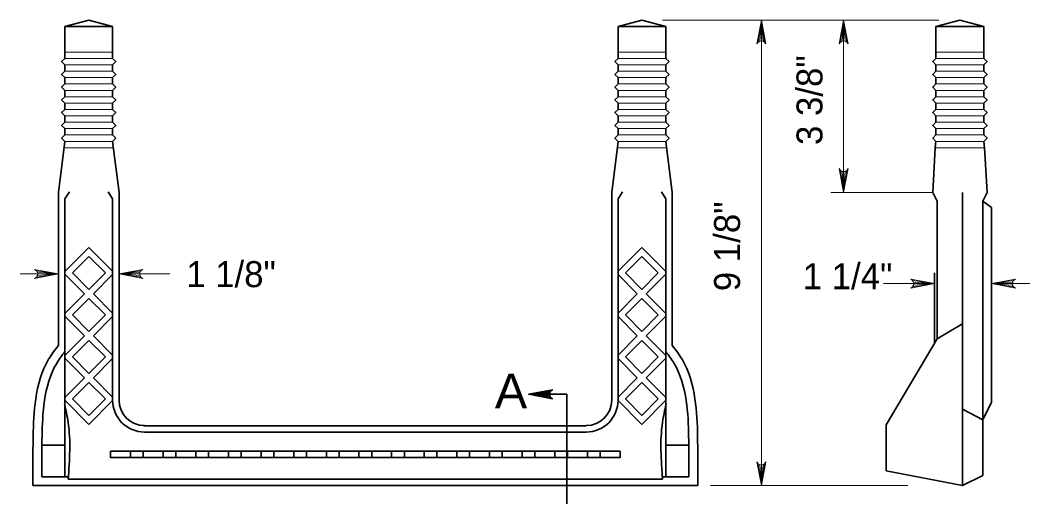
# Model space of a CAD drawing. Extents: x 15 to 140, y -57 to 117.
# Drawn here: x 96.58 to 136.22, y 36.32 to 55.01 of the extents above; entities that cross this region are included whole.
import ezdxf
from ezdxf.enums import TextEntityAlignment as Align

# ---------------------------------------------------------------- set-up
doc = ezdxf.new("R2010")
doc.units = 0
doc.header["$LTSCALE"] = 0.41
for name, color, linetype, lineweight in [('1', 7, 'Continuous', 35), ('10', 7, 'Continuous', 13), ('12', 7, 'Continuous', 53), ('13', 7, 'Continuous', 53), ('6', 7, 'Continuous', 13)]:
    doc.layers.add(name, color=color, linetype=linetype, lineweight=lineweight)

msp = doc.modelspace()

# ---------------------------------------------------------------- linework, layer by layer
at = {"layer": '1'}
for p, q in [((98.332, 54.7556), (100.2119, 54.7556)), ((98.332, 53.5056), (98.332, 54.7556)), ((100.2119, 53.5056), (100.2119, 54.7556)), ((121.9346, 54.7556), (120.0548, 54.7556)), ((120.0548, 53.5056), (120.0548, 54.7556)), ((121.9346, 53.5056), (121.9346, 54.7556)), ((134.4166, 54.7556), (132.5368, 54.7556)), ((132.5368, 53.5056), (132.5368, 54.7556)), ((134.4166, 53.5056), (134.4166, 54.7556)), ((98.332, 53.0056), (98.332, 53.2556)), ((100.2119, 53.0056), (100.2119, 53.2556)), ((120.0548, 53.0056), (120.0548, 53.2556)), ((121.9346, 53.0056), (121.9346, 53.2556)), ((132.5368, 53.0056), (132.5368, 53.2556)), ((134.4166, 53.0056), (134.4166, 53.2556)), ((98.332, 52.5056), (98.332, 52.7556)), ((100.2119, 52.5056), (100.2119, 52.7556)), ((120.0548, 52.5056), (120.0548, 52.7556)), ((121.9346, 52.5056), (121.9346, 52.7556)), ((132.5368, 52.5056), (132.5368, 52.7556)), ((134.4166, 52.5056), (134.4166, 52.7556)), ((98.332, 52.0056), (98.332, 52.2556)), ((100.2119, 52.0056), (100.2119, 52.2556)), ((120.0548, 52.0056), (120.0548, 52.2556)), ((121.9346, 52.0056), (121.9346, 52.2556)), ((132.5368, 52.0056), (132.5368, 52.2556)), ((134.4166, 52.0056), (134.4166, 52.2556)), ((98.332, 51.5056), (98.332, 51.7556)), ((100.2119, 51.5056), (100.2119, 51.7556)), ((120.0548, 51.5056), (120.0548, 51.7556)), ((121.9346, 51.5056), (121.9346, 51.7556)), ((132.5368, 51.5056), (132.5368, 51.7556)), ((134.4166, 51.5056), (134.4166, 51.7556)), ((98.332, 51.0056), (98.332, 51.2556)), ((100.2119, 51.0056), (100.2119, 51.2556)), ((120.0548, 51.0056), (120.0548, 51.2556)), ((121.9346, 51.0056), (121.9346, 51.2556)), ((132.5368, 51.0056), (132.5368, 51.2556)), ((134.4166, 51.0056), (134.4166, 51.2556)), ((98.332, 50.5056), (98.332, 50.7556)), ((100.2119, 50.5056), (100.2119, 50.7556)), ((120.0548, 50.5056), (120.0548, 50.7556)), ((121.9346, 50.5056), (121.9346, 50.7556)), ((132.5368, 50.5056), (132.5368, 50.7556)), ((134.4166, 50.5056), (134.4166, 50.7556)), ((98.082, 48.2556), (98.332, 50.2556)), ((100.4619, 48.2556), (100.2119, 50.2556)), ((119.8048, 48.2556), (120.0548, 50.2556)), ((122.1846, 48.2556), (121.9346, 50.2556)), ((132.4118, 48.2556), (132.5055, 50.0056)), ((132.5055, 50.0056), (132.5368, 50.2556)), ((134.4166, 50.2556), (134.4478, 50.0056)), ((134.5416, 48.2556), (134.4478, 50.0056)), ((98.082, 42.2556), (98.082, 48.2556)), ((98.332, 48.0056), (98.5123, 48.2805)), ((98.332, 37.1056), (98.332, 48.0056)), ((100.2119, 48.0056), (100.0316, 48.2805)), ((100.2119, 40.107), (100.2119, 48.0056)), ((100.4619, 40.1074), (100.4619, 48.2556)), ((119.8048, 40.1074), (119.8048, 48.2556)), ((120.0548, 48.0056), (120.2351, 48.2805)), ((120.0548, 40.107), (120.0548, 48.0056)), ((121.9346, 48.0056), (121.7544, 48.2805)), ((121.9346, 37.1056), (121.9346, 48.0056)), ((122.1846, 42.2556), (122.1846, 48.2556)), ((133.582, 36.7556), (133.582, 48.2556)), ((134.3713, 47.9131), (134.7213, 47.6553)), ((134.7213, 47.6553), (134.7213, 40.0341)), ((132.482, 42.3374), (132.482, 45.1017)), ((132.582, 42.5056), (133.5496, 43.0918)), ((130.582, 39.1423), (132.582, 42.5056)), ((134.3713, 39.3341), (133.6079, 39.7354)), ((134.3713, 39.3341), (134.7213, 40.0341)), ((101.4213, 39.1056), (118.8048, 39.1056)), ((101.4619, 38.8556), (118.8048, 38.8556)), ((130.582, 37.3387), (130.582, 39.1423)), ((97.4369, 38.3417), (98.332, 38.3417)), ((100.1333, 37.8549), (100.1333, 38.1049)), ((100.1333, 38.1049), (120.1333, 38.1049)), ((108.6024, 37.8549), (108.6024, 38.1049)), ((111.6642, 37.8549), (111.6642, 38.1049)), ((120.1333, 37.8549), (120.1333, 38.1049)), ((122.8298, 38.3417), (121.9346, 38.3417)), ((97.082, 36.7556), (97.082, 37.7556)), ((97.432, 37.1056), (97.432, 37.7556)), ((100.1333, 37.8549), (120.1333, 37.8549)), ((122.8346, 37.1056), (122.8346, 37.7556)), ((123.1846, 36.7556), (123.1846, 37.7556)), ((133.582, 36.7556), (130.582, 37.3387)), ((97.432, 37.1056), (98.4657, 37.1056)), ((98.4653, 37.0056), (121.8014, 37.0056)), ((122.8346, 37.1056), (121.801, 37.1056)), ((133.582, 36.7556), (134.3713, 37.1502)), ((97.082, 36.7556), (123.1846, 36.7556))]:
    msp.add_line(p, q, dxfattribs=at)
for points in [[(98.332, 54.7556), (99.2719, 55.0056), (100.2119, 54.7556)], [(121.9346, 54.7556), (120.9947, 55.0056), (120.0548, 54.7556)], [(134.4166, 54.7556), (133.4767, 55.0056), (132.5368, 54.7556)], [(98.332, 53.5056), (98.207, 53.3806), (98.332, 53.2556)], [(100.2119, 53.5056), (100.3369, 53.3806), (100.2119, 53.2556)], [(120.0548, 53.5056), (119.9298, 53.3806), (120.0548, 53.2556)], [(121.9346, 53.5056), (122.0596, 53.3806), (121.9346, 53.2556)], [(132.5368, 53.5056), (132.4118, 53.3806), (132.5368, 53.2556)], [(134.4166, 53.5056), (134.5416, 53.3806), (134.4166, 53.2556)], [(98.332, 53.0056), (98.207, 52.8806), (98.332, 52.7556)], [(100.2119, 53.0056), (100.3369, 52.8806), (100.2119, 52.7556)], [(120.0548, 53.0056), (119.9298, 52.8806), (120.0548, 52.7556)], [(121.9346, 53.0056), (122.0596, 52.8806), (121.9346, 52.7556)], [(132.5368, 53.0056), (132.4118, 52.8806), (132.5368, 52.7556)], [(134.4166, 53.0056), (134.5416, 52.8806), (134.4166, 52.7556)], [(98.332, 52.5056), (98.207, 52.3806), (98.332, 52.2556)], [(100.2119, 52.5056), (100.3369, 52.3806), (100.2119, 52.2556)], [(120.0548, 52.5056), (119.9298, 52.3806), (120.0548, 52.2556)], [(121.9346, 52.5056), (122.0596, 52.3806), (121.9346, 52.2556)], [(132.5368, 52.5056), (132.4118, 52.3806), (132.5368, 52.2556)], [(134.4166, 52.5056), (134.5416, 52.3806), (134.4166, 52.2556)], [(98.332, 52.0056), (98.207, 51.8806), (98.332, 51.7556)], [(100.2119, 52.0056), (100.3369, 51.8806), (100.2119, 51.7556)], [(120.0548, 52.0056), (119.9298, 51.8806), (120.0548, 51.7556)], [(121.9346, 52.0056), (122.0596, 51.8806), (121.9346, 51.7556)], [(132.5368, 52.0056), (132.4118, 51.8806), (132.5368, 51.7556)], [(134.4166, 52.0056), (134.5416, 51.8806), (134.4166, 51.7556)], [(98.332, 51.5056), (98.207, 51.3806), (98.332, 51.2556)], [(100.2119, 51.5056), (100.3369, 51.3806), (100.2119, 51.2556)], [(120.0548, 51.5056), (119.9298, 51.3806), (120.0548, 51.2556)], [(121.9346, 51.5056), (122.0596, 51.3806), (121.9346, 51.2556)], [(132.5368, 51.5056), (132.4118, 51.3806), (132.5368, 51.2556)], [(134.4166, 51.5056), (134.5416, 51.3806), (134.4166, 51.2556)], [(98.332, 51.0056), (98.207, 50.8806), (98.332, 50.7556)], [(100.2119, 51.0056), (100.3369, 50.8806), (100.2119, 50.7556)], [(120.0548, 51.0056), (119.9298, 50.8806), (120.0548, 50.7556)], [(121.9346, 51.0056), (122.0596, 50.8806), (121.9346, 50.7556)], [(132.5368, 51.0056), (132.4118, 50.8806), (132.5368, 50.7556)], [(134.4166, 51.0056), (134.5416, 50.8806), (134.4166, 50.7556)], [(98.332, 50.5056), (98.207, 50.3806), (98.332, 50.2556)], [(100.2119, 50.5056), (100.3369, 50.3806), (100.2119, 50.2556)], [(120.0548, 50.5056), (119.9298, 50.3806), (120.0548, 50.2556)], [(121.9346, 50.5056), (122.0596, 50.3806), (121.9346, 50.2556)], [(132.5368, 50.5056), (132.4118, 50.3806), (132.5368, 50.2556)], [(134.4166, 50.5056), (134.5416, 50.3806), (134.4166, 50.2556)], [(132.4118, 48.2556), (132.582, 47.9131), (132.582, 42.5056)], [(134.5416, 48.2556), (134.3713, 47.9131), (134.3713, 37.1502)]]:
    msp.add_lwpolyline(points, dxfattribs=at)
for points in [[(100.1333, 38.1049), (100.9146, 38.1049), (100.9146, 37.8549), (100.1333, 37.8549)], [(101.4146, 38.1049), (102.1959, 38.1049), (102.1959, 37.8549), (101.4146, 37.8549)], [(102.6959, 38.1049), (103.4772, 38.1049), (103.4772, 37.8549), (102.6959, 37.8549)], [(103.9772, 38.1049), (104.7585, 38.1049), (104.7585, 37.8549), (103.9772, 37.8549)], [(105.2585, 38.1049), (106.0398, 38.1049), (106.0398, 37.8549), (105.2585, 37.8549)], [(106.5398, 38.1049), (107.3211, 38.1049), (107.3211, 37.8549), (106.5398, 37.8549)], [(107.8211, 38.1049), (108.6024, 38.1049), (108.6024, 37.8549), (107.8211, 37.8549)], [(109.1024, 38.1049), (109.8837, 38.1049), (109.8837, 37.8549), (109.1024, 37.8549)], [(111.1642, 38.1049), (110.383, 38.1049), (110.383, 37.8549), (111.1642, 37.8549)], [(112.4455, 38.1049), (111.6642, 38.1049), (111.6642, 37.8549), (112.4455, 37.8549)], [(113.7268, 38.1049), (112.9456, 38.1049), (112.9456, 37.8549), (113.7268, 37.8549)], [(115.0081, 38.1049), (114.2269, 38.1049), (114.2269, 37.8549), (115.0081, 37.8549)], [(116.2894, 38.1049), (115.5082, 38.1049), (115.5082, 37.8549), (116.2894, 37.8549)], [(117.5707, 38.1049), (116.7895, 38.1049), (116.7895, 37.8549), (117.5707, 37.8549)], [(118.852, 38.1049), (118.0707, 38.1049), (118.0707, 37.8549), (118.852, 37.8549)], [(120.1333, 38.1049), (119.352, 38.1049), (119.352, 37.8549), (120.1333, 37.8549)]]:
    msp.add_lwpolyline(points, close=True, dxfattribs=at)
for centre, radius, start, end in [((101.4619, 40.107), 1.25, 180, 270), ((101.4619, 40.1074), 1, 180, 270), ((118.8048, 40.1074), 1, 270, 0), ((118.8048, 40.107), 1.25, 270, 0)]:
    msp.add_arc(centre, radius, start, end, dxfattribs=at)
for points in [[(97.082, 37.7556), (97.0897, 38.681), (97.1911, 40.1586), (97.6978, 41.7087), (98.082, 42.2556)], [(123.1846, 37.7556), (123.177, 38.681), (123.0756, 40.1586), (122.5688, 41.7087), (122.1846, 42.2556)], [(97.432, 37.7527), (97.4396, 38.6675), (97.5373, 40.0912), (98.0143, 41.5502), (98.332, 42.0026)], [(122.8346, 37.7527), (122.8271, 38.6675), (122.7294, 40.0912), (122.2524, 41.5502), (121.9346, 42.0026)], [(98.3247, 39.9456), (98.4653, 39.2421), (98.4653, 37.0051)], [(121.942, 39.9456), (121.8014, 39.2421), (121.8014, 37.0051)]]:
    msp.add_spline(points, degree=3, dxfattribs=at)
at = {"layer": '10'}
for p, q in [((121.803, 55.0056), (132.6463, 55.0056)), ((125.6846, 36.7556), (125.6846, 55.0056)), ((128.9118, 55.0056), (128.9118, 48.2556)), ((132.4118, 48.2556), (128.4118, 48.2556)), ((96.582, 45.0572), (98.082, 45.0572)), ((100.4619, 45.0572), (102.4619, 45.0572)), ((130.482, 44.6754), (132.482, 44.6754)), ((134.7213, 44.6754), (136.2213, 44.6754)), ((123.6846, 36.7556), (131.4378, 36.7556))]:
    msp.add_line(p, q, dxfattribs=at)
at = {"layer": '10', "lineweight": 35}
for p, q in [((116.5471, 40.3391), (118.0471, 40.3391)), ((118.0471, 40.3391), (118.0471, 35.3391))]:
    msp.add_line(p, q, dxfattribs=at)
at = {"layer": '10'}
for points in [[(125.6846, 55.0056), (125.8594, 54.0735), (125.8096, 54.1453), (125.7471, 54.1823), (125.6846, 54.1931), (125.6221, 54.1823), (125.5596, 54.1453), (125.5099, 54.0735), (125.6846, 55.0056), (125.5596, 54.1453), (125.6221, 54.1823), (125.6846, 55.0056), (125.6846, 54.1931), (125.7471, 54.1823), (125.6846, 55.0056), (125.8096, 54.1453)], [(128.9118, 55.0056), (129.0865, 54.0735), (129.0368, 54.1453), (128.9743, 54.1823), (128.9118, 54.1931), (128.8493, 54.1823), (128.7868, 54.1453), (128.737, 54.0735), (128.9118, 55.0056), (128.7868, 54.1453), (128.8493, 54.1823), (128.9118, 55.0056), (128.9118, 54.1931), (128.9743, 54.1823), (128.9118, 55.0056), (129.0368, 54.1453)], [(128.9118, 48.2556), (128.737, 49.1876), (128.7868, 49.1158), (128.8493, 49.0788), (128.9118, 49.0681), (128.9743, 49.0788), (129.0368, 49.1158), (129.0865, 49.1876), (128.9118, 48.2556), (129.0368, 49.1158), (128.9743, 49.0788), (128.9118, 48.2556), (128.9118, 49.0681), (128.8493, 49.0788), (128.9118, 48.2556), (128.7868, 49.1158)], [(98.082, 45.0572), (97.15, 44.8825), (97.2218, 44.9322), (97.2588, 44.9947), (97.2695, 45.0572), (97.2588, 45.1197), (97.2218, 45.1822), (97.15, 45.232), (98.082, 45.0572), (97.2218, 45.1822), (97.2588, 45.1197), (98.082, 45.0572), (97.2695, 45.0572), (97.2588, 44.9947), (98.082, 45.0572), (97.2218, 44.9322)], [(100.4619, 45.0572), (101.3939, 45.232), (101.3221, 45.1822), (101.2851, 45.1197), (101.2744, 45.0572), (101.2851, 44.9947), (101.3221, 44.9322), (101.3939, 44.8825), (100.4619, 45.0572), (101.3221, 44.9322), (101.2851, 44.9947), (100.4619, 45.0572), (101.2744, 45.0572), (101.2851, 45.1197), (100.4619, 45.0572), (101.3221, 45.1822)], [(132.482, 44.6754), (131.55, 44.5006), (131.6218, 44.5504), (131.6588, 44.6129), (131.6695, 44.6754), (131.6588, 44.7379), (131.6218, 44.8004), (131.55, 44.8501), (132.482, 44.6754), (131.6218, 44.8004), (131.6588, 44.7379), (132.482, 44.6754), (131.6695, 44.6754), (131.6588, 44.6129), (132.482, 44.6754), (131.6218, 44.5504)], [(134.7213, 44.6754), (135.6534, 44.8501), (135.5816, 44.8004), (135.5445, 44.7379), (135.5338, 44.6754), (135.5445, 44.6129), (135.5816, 44.5504), (135.6534, 44.5006), (134.7213, 44.6754), (135.5816, 44.5504), (135.5445, 44.6129), (134.7213, 44.6754), (135.5338, 44.6754), (135.5445, 44.7379), (134.7213, 44.6754), (135.5816, 44.8004)], [(125.6846, 36.7556), (125.5099, 37.6876), (125.5596, 37.6158), (125.6221, 37.5788), (125.6846, 37.5681), (125.7471, 37.5788), (125.8096, 37.6158), (125.8594, 37.6876), (125.6846, 36.7556), (125.8096, 37.6158), (125.7471, 37.5788), (125.6846, 36.7556), (125.6846, 37.5681), (125.6221, 37.5788), (125.6846, 36.7556), (125.5596, 37.6158)]]:
    msp.add_lwpolyline(points, dxfattribs=at)
at = {"layer": '10', "lineweight": 35}
msp.add_lwpolyline([(116.5471, 40.3391), (117.4791, 40.5139), (117.4073, 40.4641), (117.3703, 40.4016), (117.3596, 40.3391), (117.3703, 40.2766), (117.4073, 40.2141), (117.4791, 40.1644), (116.5471, 40.3391), (117.4073, 40.2141), (117.3703, 40.2766), (116.5471, 40.3391), (117.3596, 40.3391), (117.3703, 40.4016), (116.5471, 40.3391), (117.4073, 40.4641)], dxfattribs=at)
at = {"layer": '6'}
for p, q in [((98.332, 53.7556), (100.2119, 53.7556)), ((121.9346, 53.7556), (120.0548, 53.7556)), ((134.4166, 53.7556), (132.5368, 53.7556)), ((100.2119, 53.5056), (98.332, 53.5056)), ((98.332, 53.2556), (100.2119, 53.2556)), ((120.0548, 53.5056), (121.9346, 53.5056)), ((121.9346, 53.2556), (120.0548, 53.2556)), ((132.5368, 53.5056), (134.4166, 53.5056)), ((134.4166, 53.2556), (132.5368, 53.2556)), ((98.332, 53.0056), (100.2119, 53.0056)), ((98.332, 52.7556), (100.2119, 52.7556)), ((121.9346, 53.0056), (120.0548, 53.0056)), ((121.9346, 52.7556), (120.0548, 52.7556)), ((134.4166, 53.0056), (132.5368, 53.0056)), ((134.4166, 52.7556), (132.5368, 52.7556)), ((98.332, 52.5056), (100.2119, 52.5056)), ((121.9346, 52.5056), (120.0548, 52.5056)), ((134.4166, 52.5056), (132.5368, 52.5056)), ((98.332, 52.2556), (100.2119, 52.2556)), ((98.332, 52.0056), (100.2119, 52.0056)), ((121.9346, 52.2556), (120.0548, 52.2556)), ((121.9346, 52.0056), (120.0548, 52.0056)), ((134.4166, 52.2556), (132.5368, 52.2556)), ((134.4166, 52.0056), (132.5368, 52.0056)), ((98.332, 51.7556), (100.2119, 51.7556)), ((121.9346, 51.7556), (120.0548, 51.7556)), ((134.4166, 51.7556), (132.5368, 51.7556)), ((98.332, 51.5056), (100.2119, 51.5056)), ((98.332, 51.2556), (100.2119, 51.2556)), ((121.9346, 51.5056), (120.0548, 51.5056)), ((121.9346, 51.2556), (120.0548, 51.2556)), ((134.4166, 51.5056), (132.5368, 51.5056)), ((134.4166, 51.2556), (132.5368, 51.2556)), ((98.332, 51.0056), (100.2119, 51.0056)), ((98.332, 50.7556), (100.2119, 50.7556)), ((121.9346, 51.0056), (120.0548, 51.0056)), ((121.9346, 50.7556), (120.0548, 50.7556)), ((134.4166, 51.0056), (132.5368, 51.0056)), ((134.4166, 50.7556), (132.5368, 50.7556)), ((98.332, 50.5056), (100.2119, 50.5056)), ((121.9346, 50.5056), (120.0548, 50.5056)), ((134.4166, 50.5056), (132.5368, 50.5056)), ((98.3008, 50.0056), (100.2431, 50.0056)), ((100.2119, 50.2556), (98.332, 50.2556)), ((121.9659, 50.0056), (120.0236, 50.0056)), ((120.0548, 50.2556), (121.9346, 50.2556)), ((134.4478, 50.0056), (132.5055, 50.0056)), ((132.5368, 50.2556), (134.4166, 50.2556)), ((99.2788, 46.0953), (98.332, 45.1485)), ((100.2119, 45.1622), (99.2788, 46.0953)), ((120.0548, 45.1622), (120.9879, 46.0953)), ((120.9879, 46.0953), (121.9346, 45.1485)), ((99.2788, 45.7417), (98.6324, 45.0953)), ((99.9253, 45.0953), (99.2788, 45.7417)), ((120.3414, 45.0953), (120.9878, 45.7417)), ((120.9878, 45.7417), (121.6343, 45.0953)), ((99.102, 44.272), (98.332, 45.042)), ((99.2788, 44.4488), (98.6324, 45.0953)), ((99.9253, 45.0953), (99.2788, 44.4488)), ((100.2119, 45.0283), (99.4556, 44.272)), ((120.0548, 45.0283), (120.8111, 44.272)), ((120.3414, 45.0953), (120.9879, 44.4488)), ((120.9879, 44.4488), (121.6343, 45.0953)), ((121.1646, 44.272), (121.9346, 45.042)), ((99.102, 44.272), (98.332, 43.5021)), ((99.2788, 44.0953), (98.6323, 43.4488)), ((99.9252, 43.4488), (99.2788, 44.0953)), ((100.2119, 43.5158), (99.4556, 44.272)), ((120.0548, 43.5158), (120.8111, 44.272)), ((120.3414, 43.4488), (120.9879, 44.0953)), ((120.9879, 44.0953), (121.6343, 43.4488)), ((121.1646, 44.272), (121.9346, 43.5021)), ((99.102, 42.6256), (98.332, 43.3956)), ((99.2788, 42.8024), (98.6323, 43.4488)), ((99.9252, 43.4488), (99.2788, 42.8024)), ((100.2119, 43.3819), (99.4556, 42.6256)), ((120.0548, 43.3819), (120.8111, 42.6256)), ((120.3414, 43.4488), (120.9879, 42.8024)), ((120.9879, 42.8024), (121.6343, 43.4488)), ((121.1646, 42.6256), (121.9346, 43.3956)), ((99.102, 42.6256), (98.332, 41.8556)), ((99.2788, 42.4488), (98.6323, 41.8024)), ((99.9252, 41.8024), (99.2788, 42.4488)), ((100.2119, 41.8693), (99.4556, 42.6256)), ((120.0548, 41.8693), (120.8111, 42.6256)), ((120.3414, 41.8024), (120.9879, 42.4488)), ((120.9879, 42.4488), (121.6343, 41.8024)), ((121.1646, 42.6256), (121.9346, 41.8556)), ((99.102, 40.9791), (98.332, 41.7491)), ((99.2788, 41.1559), (98.6323, 41.8024)), ((99.9252, 41.8024), (99.2788, 41.1559)), ((100.2119, 41.7354), (99.4556, 40.9791)), ((120.0548, 41.7354), (120.8111, 40.9791)), ((120.3414, 41.8024), (120.9879, 41.1559)), ((120.9879, 41.1559), (121.6343, 41.8024)), ((121.1647, 40.9791), (121.9346, 41.7491)), ((99.102, 40.9791), (98.332, 40.2092)), ((100.2119, 40.2228), (99.4556, 40.9791)), ((120.0548, 40.2228), (120.8111, 40.9791)), ((121.1647, 40.9791), (121.9346, 40.2092)), ((99.2788, 40.8024), (98.6323, 40.1559)), ((99.9252, 40.1559), (99.2788, 40.8024)), ((120.3414, 40.1559), (120.9879, 40.8024)), ((120.9879, 40.8024), (121.6343, 40.1559)), ((99.2788, 39.1559), (98.332, 40.1027)), ((100.2119, 40.089), (99.2788, 39.1559)), ((120.0548, 40.089), (120.9879, 39.1559)), ((120.9879, 39.1559), (121.9346, 40.1027))]:
    msp.add_line(p, q, dxfattribs=at)
for points in [[(99.9252, 40.1559), (99.2788, 39.5095), (98.6323, 40.1559)], [(120.3414, 40.1559), (120.9879, 39.5095), (121.6343, 40.1559)]]:
    msp.add_lwpolyline(points, dxfattribs=at)

# ---------------------------------------------------------------- texts
at = {"layer": '12', "width": 1.05}
msp.add_text('A', height=1.36, dxfattribs=at).set_placement((115.8529, 39.7843), align=Align.CENTER)
at = {"layer": '13'}
for s, p in [('3 3/8"', (128.081, 51.8712)), ('9 1/8"', (124.8448, 46.1398))]:
    msp.add_text(s, height=1.02, rotation=90, dxfattribs=at).set_placement(p, align=Align.CENTER)
for s, p in [('1 1/8"', (104.8599, 44.5381)), ('1 1/4"', (129.0666, 44.4572))]:
    msp.add_text(s, height=1.02, dxfattribs=at).set_placement(p, align=Align.CENTER)

doc.saveas('drawing.dxf')
